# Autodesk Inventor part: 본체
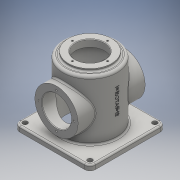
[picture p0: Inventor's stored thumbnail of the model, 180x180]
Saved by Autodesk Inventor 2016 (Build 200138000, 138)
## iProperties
Created: 2019-08
Part Number: 본체
Material: 일반
Document SubType Name: Modeling
Designer: user
Density: 1 g/cm^3
Appearance: 기본값
Author: user
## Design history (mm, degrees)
sketch "스케치1"
  geometry: L1 (70, -70)-(-70, -70); L2 (-70, -70)-(-70, 70); L3 (-70, 70)-(70, 70); L4 (70, 70)-(70, -70); L5 (70, -70)-(-70, 70); L6 (-70, -70)-(70, 70); 1 further point
  constraints: 12 end point, 2 midpoint, 2 parallel, 1 horizontal, 1 perpendicular
  dimensions: "d0" = 140 distance of L2.end L3.end; "d1" = 140 distance of L1.end L2.end
extrude "돌출1" new body sketch "스케치1" distance "d2" = 10; taper "d3" = 0 deg
fillet "모깎기1" dims "d4" = 10
hole "구멍1" diameter "d7" = 9; stored, may be unused: countersink angle "d11" = 90 deg, drill point angle "d13" = 118 deg; dims "d5" = 10, "d6" = 10, "d8" = 6, "d9" = 4, "d10" = 2, "d12" = 8
hole "구멍2" diameter "d16" = 9; stored, may be unused: countersink angle "d20" = 90 deg, drill point angle "d22" = 118 deg; dims "d14" = 10, "d15" = 10, "d17" = 6, "d18" = 4, "d19" = 2, "d21" = 8
hole "구멍3" diameter "d25" = 9; stored, may be unused: countersink angle "d29" = 90 deg, drill point angle "d31" = 118 deg; dims "d23" = 10, "d24" = 10, "d26" = 6, "d27" = 4, "d28" = 2, "d30" = 8
hole "구멍4" diameter "d34" = 9; stored, may be unused: countersink angle "d38" = 90 deg, drill point angle "d40" = 118 deg; dims "d32" = 10, "d33" = 10, "d35" = 6, "d36" = 4, "d37" = 2, "d39" = 8
sketch "스케치2"
  geometry: C1 r 50 at (0, 0); 1 further point
  constraints: 1 centre point, 1 coincident
  dimensions: "d41" = 100 diameter of C1
extrude "돌출2" join sketch "스케치2" distance "d42" = 110; taper "d43" = 0 deg
sketch "스케치3"
  geometry: C1 r 40 at (0, 0); 1 further point
  constraints: 1 centre point, 1 coincident
  dimensions: "d44" = 80 diameter of C1
extrude "돌출3" join sketch "스케치3" distance "d45" = 5; taper "d46" = 0 deg
sketch "스케치4"
  geometry: L1 (-50, 10)-(-50, 120) reference; L2 (-50, 120)-(-40, 120) reference; L3 (-40, 120)-(-40, 125) reference; L4 (-40, 125)-(40, 125) reference; L5 (40, 125)-(40, 120) reference; L6 (40, 120)-(50, 120) reference; L7 (50, 120)-(50, 10) reference; L8 (50, 10)-(70, 10) reference; L9 (70, 10)-(70, 0) reference; L10 (70, 0)-(-70, 0) reference; L11 (-70, 0)-(-70, 10) reference; L12 (-70, 10)-(-50, 10) reference; C1 r 40 at (0, 60); 2 further points
  constraints: 1 centre point, 1 coincident, 1 tangent
  dimensions: "d47" = 60 distance from line of L10 point (0, 60); "d48" = 80 diameter of C1
extrude "돌출4" join sketch "스케치4" stored distance "d49" = 124; taper "d50" = 0 deg
hole "구멍5" diameter "d53" = 54; stored, may be unused: countersink angle "d57" = 90 deg, drill point angle "d59" = 118 deg; dims "d51" = 10, "d52" = 10, "d54" = 6, "d55" = 4, "d56" = 2, "d58" = 8
hole "구멍6" diameter "d62" = 54; stored, may be unused: countersink angle "d66" = 90 deg, drill point angle "d68" = 118 deg; dims "d60" = 10, "d61" = 10, "d63" = 6, "d64" = 4, "d65" = 2, "d67" = 8
sketch "스케치5"
  geometry: C1 r 45 at (0, 0); 1 further point
  constraints: 1 centre point, 1 coincident
  dimensions: "d69" = 90 diameter of C1
extrude "돌출5" cut sketch "스케치5" distance "d70" = 112; taper "d71" = 0 deg
sketch "스케치6"
  geometry: C1 r 27 at (0, 0) reference; C2 r 40 at (0, 0) reference; 2 further points
  constraints: 1 vertical alignment
  dimensions: "d72" = 32.5 distance of point (0, 0) point (0, 32.5)
hole "구멍7" sketch "스케치6" at (0, 32.5) diameter "d73" = 3.242; stored, may be unused: countersink angle "d77" = 90 deg, drill point angle "d79" = 118 deg; dims "d74" = 8, "d75" = 4, "d76" = 2, "d78" = 10
sketch "스케치7"
  geometry: L1 (-55.969, -60)-(-55.969, -50) reference; L2 (-55.969, -50)-(55.969, -50) reference; L3 (55.969, -50)-(55.969, -60) reference; L4 (55.969, -60)-(-55.969, -60) reference; L5 (-64.031, -50)-(-64.031, -60) reference; L6 (-64.031, -60)-(-69.798, -60) reference; L7 (-69.798, -60)-(-69.798, -50) reference; L8 (-69.798, -50)-(-64.031, -50) reference; L9 (69.798, -50)-(69.798, -60) reference; L10 (69.798, -60)-(64.031, -60) reference; L11 (64.031, -60)-(64.031, -50) reference; L12 (64.031, -50)-(69.798, -50) reference; C1 r 27 at (0, 0) reference; C2 r 40 at (0, 0) reference; 2 further points
  constraints: 1 vertical alignment
  dimensions: "d83" = 32.5 distance of C1.centre point (0, 32.5)
hole "구멍8" sketch "스케치7" at (0, 32.5) diameter "d84" = 3.242; stored, may be unused: countersink angle "d88" = 90 deg, drill point angle "d90" = 118 deg; dims "d85" = 8, "d86" = 4, "d87" = 2, "d89" = 10
fillet "모깎기3" dims "d95" = 3
chamfer "모따기1" distance "d96" = 1; stored, may be unused: second distance "d97" = 2, angle "d98" = 45 deg
node "작업 평면3"
sketch "스케치10" dims "d0" = 140, "d1" = 140, "d23" = 10, "d24" = 10
  geometry: L1 (-60, 0)-(60, 0) reference; 3 further points
  constraints: 1 midpoint, 1 vertical alignment, 1 other
  dimensions: "d108" = 70 distance from line of L1 point (0, 70)
feature "엠보싱3" sketch "스케치10" dims "d0" = 140, "d1" = 140, "d109" = 0.5, "d110" = 0
fillet "모깎기4" dims "d111" = 5
fillet "모깎기5" dims "d112" = 3
fillet "모깎기6" dims "d113" = 3
node "솔리드1"
pattern_circular "원형 패턴1" dims angle "d81" = 360 deg
pattern_circular "원형 패턴2" dims angle "d92" = 360 deg
mirror "대칭1"
node "절단 모서리 투영1"
node "절단 모서리 투영2"
node "절단 모서리 투영3"
